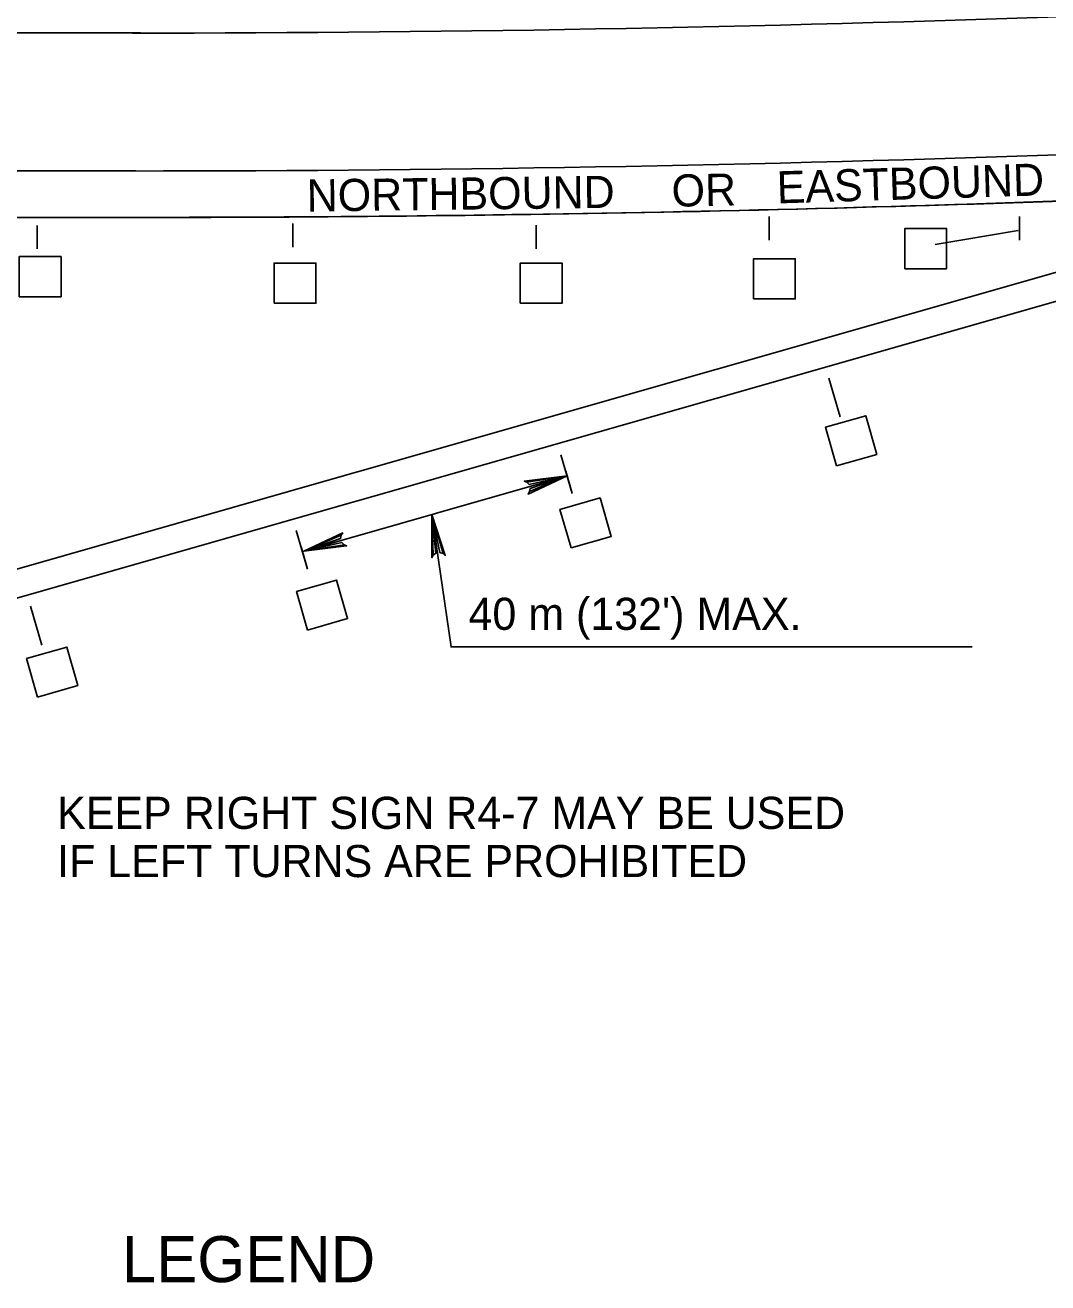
# Model space of a CAD drawing. Extents: x 640253 to 641999, y 298458 to 299646.
# Drawn here: x 641608.8 to 641704.3, y 299301.6 to 299419 of the extents above; entities that cross this region are included whole.
import ezdxf

# ---------------------------------------------------------------- set-up
doc = ezdxf.new("R2010")
doc.units = 0
doc.layers.add('2', color=7, linetype='Continuous')

msp = doc.modelspace()

# ---------------------------------------------------------------- linework, layer by layer
at = {"layer": '2'}
for p, q in [((641249.69, 299418.29), (641619.6, 299418.29)), ((641548.91, 299405.41), (641619.17, 299405.41)), ((641589.09, 299362.8), (641732.18, 299403.67)), ((641442.79, 299401.07), (641619.17, 299401.07)), ((641678.3, 299398.93), (641678.3, 299401.14)), ((641701.67, 299398.93), (641701.67, 299401.14)), ((641609.94, 299398.12), (641609.94, 299400.32)), ((641633.82, 299398.29), (641633.82, 299400.5)), ((641656.54, 299398.14), (641656.54, 299400.34)), ((641693.8, 299398.55), (641701.56, 299399.86)), ((641593.29, 299361.29), (641724.82, 299398.87)), ((641683.86, 299386.04), (641684.92, 299382.43)), ((641658.86, 299378.91), (641659.92, 299375.28)), ((641659.32, 299377.36), (641659.87, 299375.4)), ((641659.44, 299376.93), (641634.84, 299369.91)), ((641634.15, 299371.84), (641635.21, 299368.21)), ((641634.6, 299370.3), (641635.15, 299368.33)), ((641609.34, 299364.76), (641610.39, 299361.13))]:
    msp.add_line(p, q, dxfattribs=at)
for points in [[(641690.96, 299396.28), (641694.86, 299396.28), (641694.86, 299400.03), (641690.96, 299400.03)], [(641608.28, 299393.66), (641612.18, 299393.66), (641612.18, 299397.41), (641608.28, 299397.41)], [(641676.85, 299393.46), (641680.74, 299393.46), (641680.74, 299397.2), (641676.85, 299397.2)], [(641632.08, 299393.05), (641635.98, 299393.05), (641635.98, 299396.8), (641632.08, 299396.8)], [(641655.06, 299393.05), (641658.96, 299393.05), (641658.96, 299396.8), (641655.06, 299396.8)], [(641684.6, 299377.87), (641688.35, 299378.94), (641687.32, 299382.54), (641683.57, 299381.47)], [(641659.8, 299370.2), (641663.55, 299371.27), (641662.52, 299374.87), (641658.77, 299373.8)], [(641635.2, 299362.53), (641638.94, 299363.6), (641637.91, 299367.2), (641634.17, 299366.13)], [(641609.99, 299356.27), (641613.74, 299357.34), (641612.71, 299360.94), (641608.96, 299359.87)]]:
    msp.add_lwpolyline(points, close=True, dxfattribs=at)
for points in [[(641655.67, 299376.35), (641655.88, 299376.12), (641659.44, 299376.93), (641655.67, 299376.35), (641655.44, 299376.45), (641659.44, 299376.93), (641655.99, 299375.76), (641655.93, 299375.46), (641659.44, 299376.93), (641655.79, 299375.23), (641655.93, 299375.46)], [(641646.94, 299369.51), (641647.19, 299369.7), (641646.8, 299373.32), (641646.94, 299369.51), (641646.81, 299369.29), (641646.8, 299373.32), (641647.56, 299369.76), (641647.85, 299369.67), (641646.8, 299373.32), (641648.06, 299369.5), (641647.85, 299369.67)], [(641697.25, 299360.96), (641648.6, 299360.96), (641646.8, 299373.32)], [(641638.61, 299370.5), (641638.4, 299370.72), (641634.84, 299369.91), (641638.61, 299370.5), (641638.84, 299370.39), (641634.84, 299369.91), (641638.29, 299371.08), (641638.35, 299371.38), (641634.84, 299369.91), (641638.49, 299371.61), (641638.35, 299371.38)]]:
    msp.add_lwpolyline(points, dxfattribs=at)
for radius, end in [(2448.22, 274.31789), (2461.1, 274.29526), (2465.44, 272.72047), (2465.43, 272.63682)]:
    msp.add_arc((641618.76, 301866.5), radius, 270.0023, end, dxfattribs=at)

# ---------------------------------------------------------------- texts
for s, rotation, p in [('EASTBOUND', 1.7407, (641679.05, 299402.37)), ('NORTHBOUND', 0.7104, (641635.14, 299401.61)), ('OR', 1.2267, (641669.22, 299402.06))]:
    msp.add_text(s, height=3, rotation=rotation, dxfattribs=at).set_placement(p)
for s, height, p in [("40 m (132') MAX.", 3, (641650.23, 299362.55)), ('KEEP RIGHT SIGN R4-7 MAY BE USED', 3, (641611.82, 299343.96)), ('IF LEFT TURNS ARE PROHIBITED', 3, (641611.82, 299339.46)), ('LEGEND', 4.3, (641617.87, 299301.63))]:
    msp.add_text(s, height=height, dxfattribs=at).set_placement(p)

doc.saveas('drawing.dxf')
